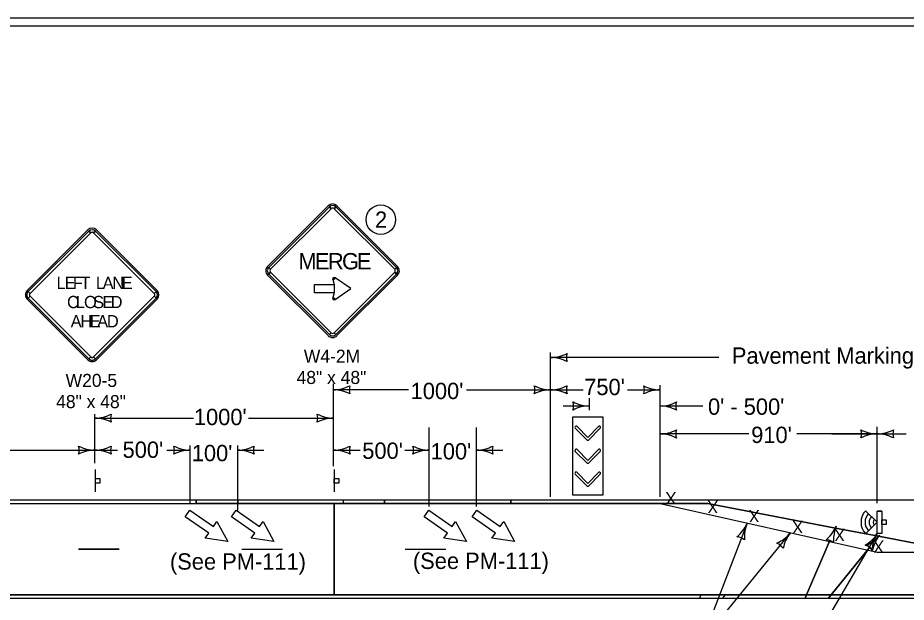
# Model space of a CAD drawing. Extents: x 10133 to 81668, y 4177 to 11018.
# Drawn here: x 25399 to 26486, y 9228 to 9944 of the extents above; entities that cross this region are included whole.
import ezdxf

# ---------------------------------------------------------------- set-up
doc = ezdxf.new("R2010")
doc.units = 0
for name, color, linetype in [('dsnNonPlotable', 7, 'Continuous'), ('dsnStdBlockModified', 7, 'Continuous'), ('dsnStdDimension', 7, 'Continuous'), ('dsnStdLabel', 7, 'Continuous'), ('dsnStdLineWork', 7, 'Continuous'), ('dsnStdNote', 7, 'Continuous'), ('Level 2', 7, 'Continuous'), ('SheetBorder', 7, 'Continuous')]:
    doc.layers.add(name, color=color, linetype=linetype)

msp = doc.modelspace()

# ---------------------------------------------------------------- linework, layer by layer
at = {"layer": 'dsnNonPlotable'}
for p, q in [((25778.9, 9713.7), (25704.6, 9639.4)), ((25780.2, 9712.3), (25782.4, 9710.1)), ((25786, 9710.1), (25788.2, 9712.3)), ((25863.7, 9639.4), (25789.5, 9713.7)), ((25484.6, 9684.1), (25410.3, 9609.8)), ((25485.9, 9682.7), (25488.1, 9680.5)), ((25491.6, 9680.5), (25493.9, 9682.7)), ((25569.4, 9609.8), (25495.2, 9684.1)), ((25708.2, 9635.9), (25706, 9638.1)), ((25862.4, 9638.1), (25860.2, 9635.9)), ((25704.6, 9628.8), (25778.9, 9554.6)), ((25706, 9630.1), (25708.2, 9632.4)), ((25786.2, 9623.8), (25787.3, 9625.5)), ((25789.5, 9554.6), (25863.7, 9628.8)), ((25860.2, 9632.4), (25862.4, 9630.1)), ((25784.3, 9623.2), (25786.2, 9623.8)), ((25413.9, 9606.3), (25411.7, 9608.5)), ((25568.1, 9608.5), (25565.9, 9606.3)), ((25410.3, 9599.2), (25484.6, 9525)), ((25411.7, 9600.5), (25413.9, 9602.8)), ((25495.2, 9525), (25569.4, 9599.2)), ((25565.9, 9602.8), (25568.1, 9600.5)), ((25786.2, 9600.7), (25784.3, 9601.3)), ((25787.3, 9599), (25786.2, 9600.7)), ((25782.4, 9558.1), (25780.2, 9555.9)), ((25788.2, 9555.9), (25786, 9558.1)), ((25488.1, 9528.5), (25485.9, 9526.3)), ((25493.9, 9526.3), (25491.6, 9528.5)), ((26097.8, 9427.1), (26111.8, 9441.2)), ((26097.8, 9398.8), (26111.8, 9412.9)), ((25493.7, 9390.6), (25493.7, 9363.1)), ((25786, 9390.6), (25786, 9363.1)), ((26097.8, 9370.8), (26111.8, 9384.9)), ((26456.4, 9339.7), (26456.4, 9312.2))]:
    msp.add_line(p, q, dxfattribs=at)
for points in [[(25780.2, 9712.3), (25706, 9638.1), (25708.2, 9635.9), (25782.4, 9710.1), (25780.2, 9712.3)], [(25862.4, 9638.1), (25788.2, 9712.3), (25786, 9710.1), (25860.2, 9635.9), (25862.4, 9638.1)], [(25485.9, 9682.7), (25411.7, 9608.5), (25413.9, 9606.3), (25488.1, 9680.5), (25485.9, 9682.7)], [(25568.1, 9608.5), (25493.9, 9682.7), (25491.6, 9680.5), (25565.9, 9606.3), (25568.1, 9608.5)], [(25706, 9630.1), (25780.2, 9555.9), (25782.4, 9558.1), (25708.2, 9632.4), (25706, 9630.1)], [(25806.5, 9612.2), (25787.3, 9625.5), (25786.2, 9623.8), (25784.3, 9623.2), (25786.3, 9617.2), (25786.3, 9607.2), (25784.3, 9601.3), (25786.2, 9600.7), (25787.3, 9599), (25806.5, 9612.2)], [(25788.2, 9555.9), (25862.4, 9630.1), (25860.2, 9632.4), (25786, 9558.1), (25788.2, 9555.9)], [(25761.9, 9607.2), (25761.9, 9617.2), (25786.3, 9617.2), (25786.3, 9607.2), (25761.9, 9607.2)], [(25411.7, 9600.5), (25485.9, 9526.3), (25488.1, 9528.5), (25413.9, 9602.8), (25411.7, 9600.5)], [(25493.9, 9526.3), (25568.1, 9600.5), (25565.9, 9602.8), (25491.6, 9528.5), (25493.9, 9526.3)], [(26114.9, 9455.2), (26114.9, 9359.2), (26078.2, 9359.2), (26078.2, 9455.2)], [(25493.8, 9374.1), (25493.8, 9379.7), (25499.4, 9379.7), (25499.4, 9374.1)], [(25786.1, 9374.1), (25786.1, 9379.7), (25791.7, 9379.7), (25791.7, 9374.1)], [(26450.8, 9312.2), (26450.8, 9339.7), (26456.4, 9339.7), (26456.4, 9312.2)], [(26456.4, 9323.3), (26456.4, 9328.9), (26462, 9328.9), (26462, 9323.3)]]:
    msp.add_lwpolyline(points, close=True, dxfattribs=at)
for points in [[(26081.3, 9441.2), (26081.3, 9441.1), (26095.4, 9427.1), (26095.4, 9427)], [(26109.5, 9443.5), (26109.5, 9443.4), (26096.6, 9429.9), (26083.7, 9443.4)], [(26081.3, 9413), (26081.3, 9412.9), (26095.4, 9398.8), (26095.4, 9398.8)], [(26109.5, 9415.3), (26109.5, 9415.2), (26096.6, 9401.6), (26083.7, 9415.2)], [(26109.5, 9387.2), (26109.5, 9387.1), (26096.6, 9373.6), (26083.7, 9387.1)], [(26081.3, 9384.9), (26081.3, 9384.8), (26095.4, 9370.8), (26095.4, 9370.7)]]:
    msp.add_lwpolyline(points, dxfattribs=at)
for centre, radius, start, end in [((25784.2, 9708.4), 7.5, 45, 134.9997), ((25784.2, 9708.4), 5.62, 45, 134.9997), ((25784.2, 9708.4), 2.5, 45, 134.9997), ((25489.9, 9678.8), 7.5, 45, 134.9997), ((25489.9, 9678.8), 5.62, 45, 134.9997), ((25489.9, 9678.8), 2.5, 45, 134.9997), ((25709.9, 9634.1), 7.5, 134.9997, 225), ((25709.9, 9634.1), 5.62, 134.9997, 225), ((25709.9, 9634.1), 2.5, 134.9997, 225), ((25858.4, 9634.1), 2.5, 315.0002, 44.9998), ((25858.4, 9634.1), 5.62, 315.0002, 44.9998), ((25858.4, 9634.1), 7.5, 315.0002, 44.9998), ((25786.2, 9623.8), 2.03, 57.6877, 198.5814), ((25415.6, 9604.5), 7.5, 134.9997, 225), ((25415.6, 9604.5), 5.62, 134.9997, 225), ((25415.6, 9604.5), 2.5, 134.9997, 225), ((25564.1, 9604.5), 2.5, 315.0002, 44.9998), ((25564.1, 9604.5), 5.62, 315.0002, 44.9998), ((25564.1, 9604.5), 7.5, 315.0002, 44.9998), ((25786.2, 9600.7), 2.03, 161.4183, 302.3126), ((25784.2, 9559.9), 7.5, 225, 315.0002), ((25784.2, 9559.9), 5.62, 225, 315.0002), ((25784.2, 9559.9), 2.5, 225, 315.0002), ((25489.9, 9530.3), 2.5, 225, 315.0002), ((25489.9, 9530.3), 7.5, 225, 315.0002), ((25489.9, 9530.3), 5.62, 225, 315.0002), ((26082.5, 9442.3), 1.65, 42.6398, 223.799), ((26110.7, 9442.3), 1.65, 314.719, 134.9025), ((26096.6, 9428.2), 1.65, 225.3902, 315.8384), ((26082.5, 9414.1), 1.65, 42.6398, 223.799), ((26110.7, 9414.1), 1.65, 314.719, 134.9025), ((26096.6, 9400), 1.65, 225.3902, 315.8384), ((26082.5, 9386), 1.65, 42.6398, 223.799), ((26110.7, 9386), 1.65, 314.719, 134.9025), ((26096.6, 9371.9), 1.65, 225.3902, 315.8384)]:
    msp.add_arc(centre, radius, start, end, dxfattribs=at)
at = {"layer": 'dsnStdBlockModified'}
msp.add_lwpolyline([(24532.5, 9934), (27667.5, 9934), (27667.5, 7924), (24532.5, 7924)], close=True, dxfattribs=at)
at = {"layer": 'dsnStdDimension'}
for p, q in [((25617.2, 9353.1), (24572.8, 9353.1)), ((25609.9, 9353.1), (24572.8, 9353.1)), ((25609.9, 9349.1), (25609.9, 9353.1)), ((25617.2, 9349.1), (25617.2, 9353.1)), ((25668.1, 9353.1), (25617.2, 9353.1)), ((25617.2, 9353.1), (25617.2, 9349.1)), ((25902.5, 9353.1), (25668.1, 9353.1)), ((25668.1, 9353.1), (25668.1, 9349.1)), ((25668.1, 9349.1), (25668.1, 9353.1)), ((25847.9, 9353.1), (25797.1, 9353.1)), ((25797.1, 9353.1), (25797.1, 9349.1)), ((26002.5, 9353.1), (25847.9, 9353.1)), ((25847.9, 9353.1), (25847.9, 9349.1)), ((25847.9, 9349.1), (25847.9, 9353.1)), ((26002.5, 9353.1), (25847.9, 9353.1)), ((25847.9, 9353.1), (25847.9, 9349.1)), ((25902.5, 9349.1), (25902.5, 9353.1)), ((26002.5, 9349.1), (26002.5, 9353.1)), ((26002.5, 9349.1), (26002.5, 9353.1)), ((26833.2, 9353.1), (26002.5, 9353.1)), ((26002.5, 9353.1), (26002.5, 9349.1)), ((24576.8, 9349.1), (25609.9, 9349.1)), ((25617.2, 9349.1), (25668.1, 9349.1)), ((25668.1, 9349.1), (25902.5, 9349.1)), ((25786, 9237.1), (25786, 9349.1)), ((25847.9, 9349.1), (25786, 9349.1)), ((25786, 9349.1), (25786, 9237.1)), ((25797.1, 9349.1), (25847.9, 9349.1)), ((25847.9, 9349.1), (26002.5, 9349.1)), ((25847.9, 9349.1), (26002.5, 9349.1)), ((26002.5, 9349.1), (25847.9, 9349.1)), ((26243.4, 9349.1), (26002.5, 9349.1)), ((26002.5, 9349.1), (26243.4, 9349.1)), ((26399.6, 9319), (26243.4, 9349.1)), ((26243.4, 9349.1), (26399.6, 9319)), ((26399.7, 9319), (26452.5, 9308.9)), ((26452.5, 9308.9), (26399.7, 9319)), ((26364.3, 9237.1), (26393, 9303.6)), ((26393, 9303.6), (26364.3, 9237)), ((26452.6, 9308.8), (26554.1, 9289.3)), ((26554.1, 9289.3), (26452.6, 9308.8)), ((26394.3, 9237), (26441.6, 9295.4)), ((26441.6, 9295.4), (26394.3, 9237)), ((26364.3, 9237.1), (24568.8, 9237.1)), ((24568.8, 9237.1), (25786, 9237.1)), ((25786, 9237.1), (26364.3, 9237.1)), ((26235.1, 9237.1), (26233.5, 9233.1)), ((26265.2, 9237.1), (26235.1, 9237.1)), ((26262, 9233.1), (26265.2, 9237.1)), ((26362.6, 9233.1), (26364.3, 9237.1)), ((26364.3, 9237.1), (26362.6, 9233.1)), ((26394.3, 9237.1), (26364.3, 9237.1)), ((26364.3, 9237), (26394.3, 9237)), ((26394.3, 9237.1), (26391.1, 9233.1)), ((26391.1, 9233.1), (26394.3, 9237.1)), ((26630.6, 9237.1), (26394.3, 9237.1)), ((24572.8, 9233.1), (26391.1, 9233.1)), ((24572.8, 9233.1), (26362.6, 9233.1)), ((26233.5, 9233.1), (26262, 9233.1)), ((26362.6, 9233.1), (26391.1, 9233.1)), ((26391.1, 9233.1), (26627.6, 9233.1))]:
    msp.add_line(p, q, dxfattribs=at)
for points in [[(25786, 9349.1), (25668.1, 9349.1), (25617.2, 9349.1)], [(26400.2, 9320.4), (26400.6, 9321.2), (26400.6, 9321.2)], [(26400.2, 9320.4), (26400.2, 9320.4)], [(26453.3, 9309.8), (26453.7, 9310.3), (26453.7, 9310.3)], [(26452.6, 9308.8), (26452.5, 9308.9)], [(26394.3, 9237), (26603.1, 9237), (26698.2, 9237)]]:
    msp.add_lwpolyline(points, dxfattribs=at)
for centre, radius, start, end in [((26361.4, 9337.6), 42.5, 309.2655, 336.072), ((26361.4, 9337.6), 42.5, 334.0959, 336.072), ((26439.8, 9304.8), 42.5, 157.3556, 160.5422), ((26439.8, 9304.8), 42.5, 158.6034, 160.5422), ((26361.4, 9337.6), 42.5, 337.3204, 337.338), ((26361.4, 9337.6), 42.5, 309.2655, 334.0959), ((26439.8, 9304.8), 42.5, 160.5422, 185.4105), ((26439.8, 9304.8), 42.5, 160.5422, 185.4105), ((26420.5, 9336.8), 42.5, 318.8219, 320.5615), ((26486.9, 9283.8), 42.5, 141.4294, 143.9415), ((26420.5, 9336.8), 42.5, 321.3942, 321.4118), ((26386.8, 9288.3), 16.4, 68.0792, 85.0713), ((26386.8, 9288.3), 16.4, 49.6046, 85.0713), ((26386.8, 9288.3), 16.4, 49.6046, 68.0792), ((26420.5, 9336.8), 42.5, 293.3393, 318.8219), ((26420.5, 9336.8), 42.5, 293.3393, 318.8219), ((26486.9, 9283.8), 42.5, 143.9415, 169.4842), ((26486.9, 9283.8), 42.5, 143.9415, 169.4842), ((26431.5, 9282.5), 16.4, 51.9095, 69.1451), ((26431.5, 9282.5), 16.4, 33.6784, 69.1451), ((26431.5, 9282.5), 16.4, 33.6784, 51.9095)]:
    msp.add_arc(centre, radius, start, end, dxfattribs=at)
at = {"layer": 'dsnStdLabel'}
for p, q in [((24576.8, 9349.1), (26185, 9349.1)), ((26185, 9349.1), (26450.8, 9289.3)), ((25603.8, 9332.6), (25609.6, 9340.8)), ((25632.5, 9312.5), (25603.8, 9332.6)), ((25609.6, 9340.8), (25638.2, 9320.7)), ((25660.4, 9332.6), (25666.1, 9340.8)), ((25689, 9312.5), (25660.4, 9332.6)), ((25666.1, 9340.8), (25694.8, 9320.7)), ((25896.1, 9332.6), (25901.9, 9340.8)), ((25924.8, 9312.5), (25896.1, 9332.6)), ((25901.9, 9340.8), (25930.5, 9320.7)), ((25954.9, 9332.6), (25960.6, 9340.8)), ((25983.5, 9312.5), (25954.9, 9332.6)), ((25960.6, 9340.8), (25989.3, 9320.7)), ((25638.2, 9320.7), (25642.5, 9326.9)), ((25642.5, 9326.9), (25655.8, 9302.3)), ((25694.8, 9320.7), (25699.1, 9326.9)), ((25699.1, 9326.9), (25712.4, 9302.3)), ((25930.5, 9320.7), (25934.8, 9326.9)), ((25934.8, 9326.9), (25948.1, 9302.3)), ((25989.3, 9320.7), (25993.6, 9326.9)), ((25993.6, 9326.9), (26006.9, 9302.3)), ((25628.2, 9306.4), (25632.5, 9312.5)), ((25684.7, 9306.4), (25689, 9312.5)), ((25920.5, 9306.4), (25924.8, 9312.5)), ((25979.2, 9306.4), (25983.5, 9312.5)), ((25655.8, 9302.3), (25628.2, 9306.4)), ((25712.4, 9302.3), (25684.7, 9306.4)), ((25948.1, 9302.3), (25920.5, 9306.4)), ((26006.9, 9302.3), (25979.2, 9306.4)), ((26450.8, 9289.3), (26599, 9289.3)), ((24568.8, 9237), (26597.2, 9237))]:
    msp.add_line(p, q, dxfattribs=at)
for points in [[(25473, 9293.5), (25523, 9293.5)], [(25473, 9293.1), (25523, 9293.1)], [(25673, 9293.1), (25723, 9293.1)], [(25673, 9293.1), (25723, 9293.1)], [(25873, 9293.1), (25923, 9293.1)]]:
    msp.add_lwpolyline(points, dxfattribs=at)
at = {"layer": 'dsnStdLineWork'}
for p, q in [((26436.7, 9340.1), (26450.8, 9326)), ((26456.4, 9339.7), (26450.8, 9339.7)), ((26450.8, 9326), (26436.7, 9311.8)), ((26456.4, 9312.2), (26450.8, 9312.2))]:
    msp.add_line(p, q, dxfattribs=at)
for radius, start, end in [(20.3, 135.88, 224.0313), (15.3, 136.1665, 223.7159), (10.3, 136.7294, 223.0963), (5.32, 138.7005, 221.2995)]:
    msp.add_arc((26451.3, 9326), radius, start, end, dxfattribs=at)
at = {"layer": 'dsnStdNote'}
for p, q in [((26051.1, 9357.2), (26051.1, 9533.8)), ((26257.1, 9527.8), (26051.2, 9527.8)), ((25785.3, 9394.8), (25785.3, 9495.5)), ((25876.9, 9488.3), (25785.3, 9488.3)), ((25948.1, 9488.3), (26051.1, 9488.3)), ((26051.1, 9488.3), (26091.1, 9488.3)), ((26145, 9488.3), (26185, 9488.3)), ((26185, 9357.2), (26185, 9493.9)), ((26098.5, 9463.2), (26098.5, 9478.1)), ((26066.5, 9468.5), (26098.5, 9468.5)), ((26237.5, 9468.4), (26185, 9468.4)), ((25493.1, 9453.6), (25613.8, 9453.6)), ((25493.3, 9398.6), (25493.3, 9458.6)), ((25681.4, 9453.6), (25785.3, 9453.6)), ((25902.5, 9345.4), (25902.5, 9442.3)), ((25960.4, 9345.4), (25960.4, 9442.3)), ((26450.8, 9349.3), (26450.8, 9442.9)), ((26293.8, 9434.2), (26185, 9434.2)), ((26452.5, 9434.3), (26352.5, 9434.3)), ((26395.2, 9434.3), (26486.1, 9434.3)), ((25609.9, 9348.8), (25609.9, 9420)), ((25668.1, 9340.6), (25668.1, 9420)), ((25376.7, 9414.4), (25493.1, 9414.4)), ((25493.9, 9414.4), (25521, 9414.4)), ((25581.3, 9414.4), (25609.9, 9414.4)), ((25668.1, 9414.4), (25700.1, 9414.4)), ((25786.2, 9414.4), (25818, 9414.4)), ((25872.5, 9414.4), (25902.5, 9414.4)), ((25960.4, 9414.4), (25992.4, 9414.4)), ((26291.6, 9324.8), (26236, 9180.3)), ((26344.4, 9312.9), (26236, 9180.3)), ((26450.8, 9312.2), (26380.7, 9193))]:
    msp.add_line(p, q, dxfattribs=at)
for centre, radius, start, end in [((26051.2, 9570.3), 42.5, 270, 298.0725), ((26051.2, 9485.3), 42.5, 61.9275, 90), ((26086.8, 9527.8), 16.4, 162.2666, 197.7334), ((25785.3, 9530.8), 42.5, 270, 298.0725), ((25785.3, 9445.8), 42.5, 61.9275, 90), ((25821, 9488.3), 16.4, 162.2666, 197.7334), ((26015.5, 9488.3), 16.4, 342.2666, 17.7334), ((26051.1, 9530.8), 42.5, 241.9275, 270), ((26051.1, 9445.8), 42.5, 90, 118.0725), ((26051.1, 9530.8), 42.5, 270, 298.0725), ((26051.1, 9445.8), 42.5, 61.9275, 90), ((26086.8, 9488.3), 16.4, 162.2666, 197.7334), ((26149.4, 9488.2), 16.4, 342.2666, 17.7334), ((26185, 9530.7), 42.5, 241.9275, 270), ((26185, 9445.7), 42.5, 90, 118.0725), ((26062.8, 9468.5), 16.4, 342.2666, 17.7334), ((26098.5, 9511), 42.5, 241.9275, 270), ((26185, 9510.9), 42.5, 270, 298.0725), ((26220.7, 9468.4), 16.4, 162.2666, 197.7334), ((26098.5, 9426), 42.5, 90, 118.0725), ((26185, 9425.9), 42.5, 61.9275, 90), ((25493.3, 9496.1), 42.5, 270, 298.0725), ((25493.3, 9411.1), 42.5, 61.9275, 90), ((25528.9, 9453.6), 16.4, 162.2666, 197.7334), ((25749.7, 9453.6), 16.4, 342.2666, 17.7334), ((25785.3, 9496.1), 42.5, 241.9275, 270), ((25785.3, 9411.1), 42.5, 90, 118.0725), ((26185, 9476.7), 42.5, 270, 298.0725), ((26185, 9391.7), 42.5, 61.9275, 90), ((26220.7, 9434.2), 16.4, 162.2666, 197.7334), ((26415.2, 9434.3), 16.4, 342.2666, 17.7334), ((26450.8, 9476.8), 42.5, 241.9275, 270), ((26450.8, 9391.8), 42.5, 90, 118.0725), ((26450.8, 9476.8), 42.5, 270, 298.0725), ((26450.8, 9391.8), 42.5, 61.9275, 90), ((26486.4, 9434.3), 16.4, 162.2666, 197.7334), ((25457.6, 9414.4), 16.4, 342.2666, 17.7334), ((25493.3, 9456.9), 42.5, 241.9275, 270), ((25493.3, 9456.9), 42.5, 270, 298.0725), ((25528.9, 9414.4), 16.4, 162.2666, 197.7334), ((25574.2, 9414.4), 16.4, 342.2666, 17.7334), ((25609.9, 9456.9), 42.5, 241.9275, 270), ((25668.1, 9456.9), 42.5, 270, 298.0725), ((25703.7, 9414.4), 16.4, 162.2666, 197.7334), ((25785.6, 9456.9), 42.5, 270, 298.0725), ((25821.2, 9414.4), 16.4, 162.2666, 197.7334), ((25866.9, 9414.4), 16.4, 342.2666, 17.7334), ((25902.5, 9456.9), 42.5, 241.9275, 270), ((25960.4, 9456.9), 42.5, 270, 298.0725), ((25996, 9414.4), 16.4, 162.2666, 197.7334), ((25493.3, 9371.9), 42.5, 90, 118.0725), ((25493.3, 9371.9), 42.5, 61.9275, 90), ((25609.9, 9371.9), 42.5, 90, 118.0725), ((25668.1, 9371.9), 42.5, 61.9275, 90), ((25785.6, 9371.9), 42.5, 61.9275, 90), ((25902.5, 9371.9), 42.5, 90, 118.0725), ((25960.4, 9371.9), 42.5, 61.9275, 90), ((26252.3, 9341.2), 42.5, 309.2655, 337.338), ((26330.8, 9308.4), 42.5, 157.338, 185.4105), ((26311.1, 9339.4), 42.5, 293.3393, 321.4118), ((26377.6, 9286.3), 42.5, 141.4118, 169.4842), ((26414.6, 9334.5), 42.5, 300.2855, 328.358), ((26487, 9289.9), 42.5, 148.358, 176.4305), ((26277.8, 9291.9), 16.4, 49.6046, 85.0713), ((26322.1, 9285), 16.4, 33.6784, 69.1451), ((26432.1, 9281.9), 16.4, 40.6246, 76.0913)]:
    msp.add_arc(centre, radius, start, end, dxfattribs=at)
at = {"layer": 'Level 2'}
msp.add_circle((25843.2, 9696.7), 18, dxfattribs=at)
at = {"layer": 'SheetBorder'}
msp.add_lwpolyline([(24532.5, 9944), (27667.5, 9944), (27667.5, 7924), (24532.5, 7924)], close=True, dxfattribs=at)

# ---------------------------------------------------------------- texts
at = {"layer": 'dsnNonPlotable'}
for s, height, p in [('M', 20, (25742.3, 9635.8)), ('E', 20, (25762.5, 9635.8)), ('R', 20, (25778.5, 9635.8)), ('G', 20, (25795.7, 9635.8)), ('E', 20, (25813.9, 9635.8)), ('L', 15, (25446.3, 9611.7)), ('E', 15, (25456.3, 9611.7)), ('F', 15, (25466.3, 9611.7)), ('T', 15, (25475.5, 9611.7)), ('L', 15, (25494.4, 9611.7)), ('A', 15, (25502.7, 9611.7)), ('N', 15, (25514.6, 9611.7)), ('E', 15, (25526, 9611.7)), ('C', 15, (25459.1, 9588.3)), ('L', 15, (25469.8, 9588.3)), ('O', 15, (25479.9, 9588.3)), ('S', 15, (25491.1, 9588.3)), ('E', 15, (25502.4, 9588.3)), ('D', 15, (25512.5, 9588.3)), ('A', 15, (25463.6, 9564.8)), ('H', 15, (25475.5, 9564.8)), ('E', 15, (25486.9, 9564.8)), ('A', 15, (25496, 9564.8)), ('D', 15, (25507.9, 9564.8)), ('W4-2M', 16, (25749, 9521.4)), ('W20-5', 16, (25457.4, 9491.8)), ('48" x 48"', 16, (25740.1, 9495.4)), ('48" x 48"', 16, (25445.8, 9465.8)), ('(See PM-111)', 20, (25585.1, 9268)), ('(See PM-111)', 20, (25882.5, 9268.8))]:
    msp.add_text(s, height=height, dxfattribs=at).set_placement(p)
for p in [(26205, 9363.1), (26256.3, 9352.4), (26306.9, 9341.2), (26360.3, 9327.9), (26411.5, 9318), (26459.2, 9303.8)]:
    msp.add_text('X', height=15, rotation=180, dxfattribs=at).set_placement(p)
at = {"layer": 'dsnStdNote'}
for s, p in [('Pavement Marking Removal Limits', (26272.9, 9520.2)), ("1000'", (25879.7, 9476.9)), ("750'", (26092.2, 9481.8)), ("0' - 500'", (26243.7, 9457.7)), ("1000'", (25614.4, 9445)), ("910'", (26296.6, 9423.1)), ("500'", (25527.1, 9404.9)), ("100'", (25611.8, 9400.8)), ("500'", (25820.5, 9403.7)), ("100'", (25904.2, 9403))]:
    msp.add_text(s, height=20, dxfattribs=at).set_placement(p)
at = {"layer": 'Level 2'}
msp.add_text('2', height=20, dxfattribs=at).set_placement((25836.1, 9686.7))

doc.saveas('drawing.dxf')
